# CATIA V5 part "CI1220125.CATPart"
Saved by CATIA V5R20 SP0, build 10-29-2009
Part number: CI1220125
Bounding box of the stored display mesh (mm): x -19 to 19, y -15.368 to 155, z -21.949 to 22.289
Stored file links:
  C:\Users\Raffaele\Desktop\3D X SITO CF\BOLEX\19-INCLINED ASSEMBLY REF_CI\CI1220125.CATPart

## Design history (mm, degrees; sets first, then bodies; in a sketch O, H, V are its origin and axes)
Set1
  DatumSurface1 to DatumSurface16 "MANIFOLD_SOLID_BREP #387"
  DatumSurface17 to DatumSurface39 "MANIFOLD_SOLID_BREP #1116"
Body1 (main body)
